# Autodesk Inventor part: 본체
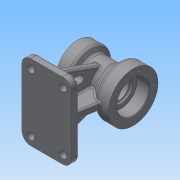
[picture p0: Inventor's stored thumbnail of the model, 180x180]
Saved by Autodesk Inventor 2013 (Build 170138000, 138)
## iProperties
Created: 2015-08
Part Number: 본체
Material: 일반
Document SubType Name: Modeling
Designer: Administrator
Density: 1 g/cm^3
Author: Administrator
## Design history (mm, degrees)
sketch "스케치1"
  geometry: L1 (0, 0)-(90, 0); L2 (0, 0)-(0, 35); L3 (0, 35)-(20, 35); L4 (20, 35)-(25.196, 26); L5 (25.196, 26)-(53.315, 26); L6 (53.315, 26)-(70, 40); L7 (70, 40)-(90, 40); L8 (90, 40)-(90, 0)
  constraints: 16 end point, 3 parallel, 2 perpendicular, 1 horizontal
  dimensions: "d0" = 90 distance of L1.start L1.end; "d1" = 70 diameter of L3 L1; "d2" = 52 diameter of L5 L1; "d3" = 80 diameter of L7 L1; "d4" = 40 deg angle of L5 L6; "d5" = 60 deg angle of L4 L5; "d6" = 20 distance of L2.end L3.end; "d7" = 20 distance of L6.end L7.end
revolve "회전1" sketch "스케치1" stored, may be unused: angle "d8" = 90 deg
sketch "스케치2"
  geometry: L1 (-61, -78)-(61, -78); L2 (61, -78)-(61, -90); L3 (61, -90)-(-61, -90); L4 (-61, -90)-(-61, -78); C1 r 35 at (0, 0) reference; 1 further point
  constraints: 8 end point, 2 parallel, 1 horizontal, 1 midpoint, 1 perpendicular, 1 vertical alignment
  dimensions: "d9" = 122 distance of L2.end L3.end; "d10" = 12 distance of L1.end L2.end; "d11" = 90 distance from line of C1.centre L3
extrude "돌출1" join sketch "스케치2" distance "d12" = 80; taper "d13" = 0 deg
node "작업 평면1"
sketch "스케치3"
  geometry: L1 (61, -78)-(61, -90) reference; L2 (61, -90)-(-61, -90) reference; L3 (-61, -90)-(-61, -78) reference; L4 (-61, -78)-(61, -78) reference; L5 (-25.091, -6.815)-(-51, -78); L6 (25.091, -6.815)-(51, -78); A1 r 26 centre (0, 0) between (-25.091, -6.815) and (25.091, -6.815) reference; 1 further point
  constraints: 4 end point, 2 point on circle, 2 point on line, 1 equal length
  dimensions: "d14" = 70 deg angle of L4 L6; "d15" = 70 deg angle of L4 L5; "d16" = 10 distance from line of L1 L6.end
extrude "돌출2" join sketch "스케치3" stored distance "d17" = 12; taper "d18" = 0 deg
sketch "스케치4"
  geometry: L1 (0, -35)-(0, 35) reference; L2 (0, 35)-(20, 35) reference; L3 (20, 35)-(25.196, 26) reference; L4 (25.196, 26)-(53.315, 26) reference; L5 (53.315, 26)-(70, 40) reference; L6 (70, 40)-(90, 40) reference; L7 (90, 40)-(90, -40) reference; L8 (90, -40)-(70, -40) reference; L9 (70, -40)-(53.315, -26) reference; L10 (53.315, -26)-(46, -26) reference; L11 (46, -26)-(46, -78) reference; L12 (46, -78)-(80, -78) reference; L13 (80, -78)-(80, -90) reference; L14 (80, -90)-(0, -90) reference; L15 (0, -90)-(0, -78) reference; L16 (0, -78)-(34, -78) reference; L17 (34, -78)-(34, -26) reference; L18 (34, -26)-(25.196, -26) reference; L19 (25.196, -26)-(20, -35) reference; L20 (20, -35)-(0, -35) reference; L21 (10, -35)-(10, -78); L22 (76.7, -40)-(70, -78); 1 further point
  constraints: 4 end point, 3 point on line, 1 midpoint, 1 perpendicular
  dimensions: "d19" = 10 distance from line of L15 L21.end; "d20" = 10 distance from line of L13 L22.end; "d21" = 80 deg angle of L12 L22
  node "절단 모서리 투영2"
feature "리브1" dims "d22" = 1, "d23" = 12, "d24" = 0, "d25" = 0, "d26" = 1, "d27" = 1
feature "리브2" dims "d28" = 1, "d29" = 12, "d30" = 0, "d31" = 0, "d32" = 1, "d33" = 1
fillet "모깎기1" dims "d34" = 14
hole "구멍1" diameter "d37" = 38; stored, may be unused: countersink angle "d41" = 90 deg, drill point angle "d43" = 0 deg; dims "d35" = 10, "d36" = 10, "d38" = 6, "d39" = 52, "d40" = 20, "d42" = 23
hole "구멍2" diameter "d46" = 32; stored, may be unused: countersink angle "d50" = 90 deg, drill point angle "d52" = 0 deg; dims "d44" = 10, "d45" = 10, "d47" = 6, "d48" = 40, "d49" = 17, "d51" = 23
fillet "모깎기2" dims "d53" = 0.3
fillet "모깎기3" dims "d54" = 3
chamfer "모따기1" distance "d55" = 1; stored, may be unused: second distance "d56" = 2, angle "d57" = 45 deg
sketch "스케치5"
  geometry: C1 r 40 at (0, 0) reference; 1 further point
  constraints: 1 vertical alignment
  dimensions: "d58" = 33 distance of point (0, 33) C1.centre
hole "구멍3" sketch "스케치5" at (0, 33) diameter "d59" = 3.242; stored, may be unused: countersink angle "d63" = 90 deg, drill point angle "d65" = 118 deg; dims "d60" = 10, "d61" = 40, "d62" = 17, "d64" = 13
sketch "스케치6"
  geometry: C1 r 35 at (0, 0) reference; 1 further point
  constraints: 1 vertical alignment
  dimensions: "d69" = 27 distance of point (0, 27) C1.centre
hole "구멍4" sketch "스케치6" at (0, 27) diameter "d70" = 3.242; stored, may be unused: countersink angle "d74" = 90 deg, drill point angle "d76" = 118 deg; dims "d71" = 10, "d72" = 40, "d73" = 17, "d75" = 13
sketch "스케치7"
  geometry: C1 r 6 at (14, 94); C2 r 6 at (66, 94); C3 r 6 at (14, 0); C4 r 6 at (66, 0); A1 r 14 centre (14, 94) between (14, 108) and (0, 94) reference; A2 r 14 centre (14, 0) between (0, 0) and (14, -14) reference; A3 r 14 centre (66, 0) between (66, -14) and (80, 0) reference; A4 r 14 centre (66, 94) between (80, 94) and (66, 108) reference; 1 further point
  constraints: 4 centre point, 4 coincident
  dimensions: "d80" = 12 diameter of C1; "d81" = 12 diameter of C2; "d82" = 12 diameter of C3; "d83" = 12 diameter of C4
extrude "돌출3" cut sketch "스케치7" stored distance "d84" = 12; taper "d85" = 0 deg
sketch "스케치8"
  geometry: L1 (47, -78)-(61, -78) reference; L2 (18, -42)-(18, -60); L3 (30, -42)-(30, -60); A1 r 26 centre (0, 0) between (6, -25.298) and (25.091, -6.815) reference; A2 r 6 centre (24, -60) between (18, -60) and (30, -60); A3 r 6 centre (24, -42) between (30, -42) and (18, -42)
  constraints: 4 end point, 4 point on circle, 4 tangent, 2 centre point, 1 vertical alignment
  dimensions: "d86" = 12 diameter of A2; "d87" = 12 diameter of A3; "d88" = 18 distance of A2.centre A3.centre; "d89" = 24 horizontal distance of A3.centre A1.centre; "d90" = 18 distance from line of A2.centre L1
extrude "돌출4" cut sketch "스케치8" stored distance "d91" = 12; taper "d92" = 0 deg
fillet "모깎기4" dims "d93" = 5
fillet "모깎기5" dims "d94" = 3
fillet "모깎기6" dims "d95" = 3
fillet "모깎기7" dims "d96" = 3
sketch "스케치9"
  geometry: L1 (-10, -3)-(1, -3) reference; L2 (-3, 37.119)-(-3, 0) reference; 2 further points
  constraints: 1 other
  dimensions: "d97" = 24 distance from line of L1 point (13, 21); "d98" = 16 distance from line of L2 point (13, 21)
feature "엠보싱1" sketch "스케치9" dims "d0" = 90, "d1" = 70, "d2" = 52, "d3" = 80, "d4" = 40 deg, "d5" = 60 deg, "d6" = 20, "d7" = 20, "d99" = 0.5, "d100" = 0
node "솔리드1"
pattern_circular "원형 패턴1" dims angle "d67" = 360 deg
pattern_circular "원형 패턴2" dims angle "d78" = 360 deg
mirror "대칭1"
node "절단 모서리 투영1"
